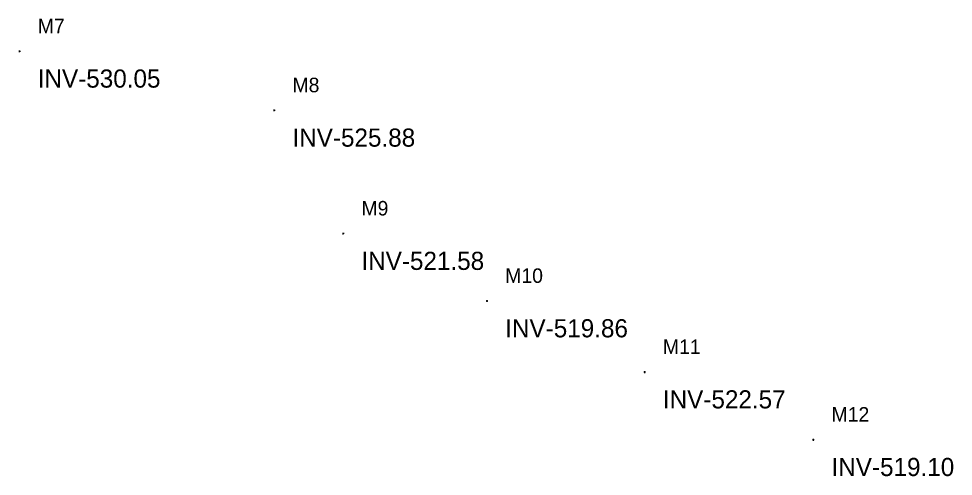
# Model space of a CAD drawing. Extents: x 1728037 to 1741597, y 649934 to 653706.
# Drawn here: x 1732798.1 to 1733055.7, y 649934 to 650060.1 of the extents above; entities that cross this region are included whole.
import ezdxf

# ---------------------------------------------------------------- set-up
doc = ezdxf.new("R2010")
doc.units = 0
for name, color, linetype in [('SURVEY - DRAINAGE - Storm Sewer - Points - Elevations', 7, 'Continuous'), ('SURVEY - DRAINAGE - Storm Sewer - Points - Locators', 7, 'Continuous'), ('SURVEY - DRAINAGE - Storm Sewer - Points - Numbers', 7, 'Continuous')]:
    doc.layers.add(name, color=color, linetype=linetype)

msp = doc.modelspace()

# ---------------------------------------------------------------- linework, layer by layer
at = {"layer": 'SURVEY - DRAINAGE - Storm Sewer - Points - Locators'}
for p, q in [((1732798.63, 650051.08), (1732798.13, 650051.08)), ((1732798.38, 650050.83), (1732798.38, 650051.33)), ((1732798.38, 650051.08), (1732798.38, 650051.08)), ((1732798.38, 650051.08), (1732798.38, 650051.08)), ((1732868.82, 650034.81), (1732868.32, 650034.81)), ((1732868.57, 650034.56), (1732868.57, 650035.06)), ((1732868.57, 650034.81), (1732868.57, 650034.81)), ((1732868.57, 650034.81), (1732868.57, 650034.81)), ((1732887.83, 650000.84), (1732887.33, 650000.84)), ((1732887.58, 650000.59), (1732887.58, 650001.09)), ((1732887.58, 650000.84), (1732887.58, 650000.84)), ((1732887.58, 650000.84), (1732887.58, 650000.84)), ((1732927.2, 649982.01), (1732927.2, 649982.51)), ((1732927.45, 649982.26), (1732926.95, 649982.26)), ((1732927.2, 649982.26), (1732927.2, 649982.26)), ((1732927.2, 649982.26), (1732927.2, 649982.26)), ((1732970.9, 649962.67), (1732970.4, 649962.67)), ((1732970.65, 649962.42), (1732970.65, 649962.92)), ((1732970.65, 649962.67), (1732970.65, 649962.67)), ((1732970.65, 649962.67), (1732970.65, 649962.67)), ((1733017.37, 649944.03), (1733016.87, 649944.03)), ((1733017.12, 649943.78), (1733017.12, 649944.28)), ((1733017.12, 649944.03), (1733017.12, 649944.03)), ((1733017.12, 649944.03), (1733017.12, 649944.03))]:
    msp.add_line(p, q, dxfattribs=at)

# ---------------------------------------------------------------- texts
at = {"layer": 'SURVEY - DRAINAGE - Storm Sewer - Points - Elevations'}
for s, p in [('INV-530.05', (1732803.38, 650041.08)), ('INV-525.88', (1732873.57, 650024.81)), ('INV-521.58', (1732892.58, 649990.84)), ('INV-519.86', (1732932.2, 649972.26)), ('INV-522.57', (1732975.65, 649952.67)), ('INV-519.10', (1733022.12, 649934.03))]:
    msp.add_text(s, height=5, dxfattribs=at).set_placement(p)
at = {"layer": 'SURVEY - DRAINAGE - Storm Sewer - Points - Numbers'}
for s, p in [('M7', (1732803.38, 650056.08)), ('M8', (1732873.57, 650039.81)), ('M9', (1732892.58, 650005.84)), ('M10', (1732932.2, 649987.26)), ('M11', (1732975.65, 649967.67)), ('M12', (1733022.12, 649949.03))]:
    msp.add_text(s, height=4, dxfattribs=at).set_placement(p)

doc.saveas('drawing.dxf')
